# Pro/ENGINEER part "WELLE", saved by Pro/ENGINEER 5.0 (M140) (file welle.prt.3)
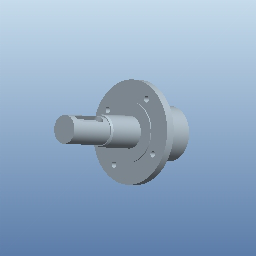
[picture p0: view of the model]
Units: millimeter Kilogram Sec (mmKs); MM, KILOGRAM, SECS
Materials in the file: RST37-2_10038

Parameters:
  MATERIAL = "1.0038;RSt37-2"
  FIRMA = "INNEO"
  BEARBEITER = "INNEO_VL"
  PRUEFER = "INNEO_VL"
  BEARB_DAT = "1.1.1111"
  PRUEF_DAT = "1.1.1111"
  MC_CHECKTYPE = "SUT_DE"
  MODEL_CHECK = "Mon Apr 24 2006 15:09:24"
  ABMESSUNG = "0.00 x 0.00 x 0.00"
  PTC_MATERIAL_NAME = "RST37-2_10038"
  PRO_UNIT_SYS = "Custom"
  SCREW_SIZE = "M6"
  METRISCH = "JA"

Other parameters: KATEGORIE, MASSE, MC_ERRORS, GEWICHT, THERM_EXPANSION_REF_TEMPERATURE, STRESS_LIMIT_FOR_TENSION, STEIGUNG, BOHRER_SPITZENWINKEL, BOHR_TIEFE, BOHR_DURCHM, GEWINDE_DURCHM, GEWINDEGÄNGE_PRO_INCH, GEWINDE_TIEFE, GEWINDE_LÄNGE

Other named items: C_T, YZ_T_RECHTS, XZ_T_OBEN, XY_T_VORNE, A_T_X, A_T_Y, A_T_Z

Layers: BEZUGSACHSEN, BEZUGSEBENEN, BOHRUNGEN, FASEN, GEWINDE, HILFEN, KURVEN, PLATZIERUNG, TEIL_STARTBEZUEGE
